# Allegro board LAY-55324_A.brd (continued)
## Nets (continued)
DCDC_3V3: C16.1 C35.1 C72.1 C73.1 C76.1 C78.1 C79.1 C85.1 C87.1 C97.1 C100.1 C102.1 C106.1 C112.1 C218.1 C225.1 C226.1 C233.1 C236.1 C238.1 C250.1 C252.1 C254.1 C261.1 C269.1 C274.1 C275.1 C278.1 C279.1 J2.36 J2.38 J3.36 J3.38 J62.1 J64.13 L1.1 L4.2 R15.1 R16.1 R22.1 R23.1 R32.1 R40.1 R41.1 R62.2 R69.1 R70.1 R71.1 R215.1 R216.1 R218.1 R286.1 R297.1 R298.1 R302.1 R307.1 R311.1 R312.2 R314.1 R374.2 R376.1 R378.1 R380.1 R382.1 SW64.1 TP215.1(PIN1) U3.7 U4.E9 U4.F10 U4.J10 U4.K4 U4.L1 U4.L2 U4.M9 U4.N14 U4.P12 U203.1 U203.3 U205.1 U207.5(VCCB) U208.5(VCCB) U212.5(VCCB) U213.1 U214.5 U217.1 U221.14(REFB) Y1.1 Y1.4(VDD)
DCDC_FB: R312.1 R315.1 U3.8
DCDC_SW: L4.1 U3.3
DM: CON60.A7 CON60.B7 L60.4 U1.2
DP: CON60.A6 CON60.B6 L60.1 U1.1
G: D60.3 R82.2
GPIO_AD_B0_01: J2.28 U4.H10
GPIO_AD_B0_01_EXT: J3.28 J64.11
GPIO_AD_B0_02: J2.51 U4.M11
GPIO_AD_B0_02_EXT: J3.51 J64.8
GPIO_AD_B0_03: J2.26 U4.G11
GPIO_AD_B0_03_EXT: J3.26 J64.6
GPIO_AD_B0_04: J61.3 R21.2 R22.2 U4.F11
GPIO_AD_B0_05: J61.1 R23.2 R24.2 U4.G14
GPIO_AD_B1_04: J2.39 U4.L12
GPIO_AD_B1_04_EXT: J3.39 J64.1
GPIO_AD_B1_12: J2.31 U4.H12
GPIO_AD_B1_12_EXT: J3.31 J64.5
GPIO_AD_B1_13: J2.27 U4.H11
GPIO_AD_B1_13_EXT: J3.27 J64.9
GPIO_AD_B1_15: J2.32 U4.J14
GPIO_AD_B1_15_EXT: J3.32 J64.7
GPIO_B0_04: C123.1 R37.2 SW62.1 SW62.2 U4.C8
GPIO_B0_05: J63.2 U4.B8
GPIO_B0_06: R32.2 R35.2 U4.A8
GPIO_B0_07: R38.2 R40.2 U4.A9
GPIO_B0_08: R36.2 U4.B9
GPIO_B0_09: C37.1 R42.2 SW61.1 SW61.2 U4.C9
GPIO_B0_10: R39.2 R227.2 U4.D9
GPIO_B0_11: J2.8 R34.2 U4.A10
GPIO_B0_11_EXT: J3.8 R235.2
GPIO_B0_12: R41.2 R78.2 U4.C10
GPIO_B0_13: R31.2 U4.D10
GPIO_B0_14: J2.14 R18.2 U4.E10
GPIO_B0_14_EXT: J3.14 U213.2
GPIO_B0_15: R77.2 U4.E11 U214.3
GPIO_B1_00: R224.2 U4.A11
GPIO_B1_02: J2.7 U4.C11
GPIO_B1_02_EXT: J3.7 J64.3
GPIO_B1_03: J2.9 U4.D11
GPIO_B1_03_EXT: J3.9 J64.4
I2C1_SCL: J2.33 R16.2 TP20.1(PIN1) U4.J11
I2C1_SCL_EXT: J3.33 J64.10
I2C1_SDA: J2.37 R15.2 TP17.1(PIN1) U4.K11
I2C1_SDA_EXT: J3.37 J64.12
JTAG_NTRST: J2.23 U4.G10
JTAG_NTRST_EXT: J3.23 J62.9
JTAG_TDI: J2.19 U4.F14
JTAG_TDI_EXT: J3.19 J62.8
JTAG_TDO: J2.30 U4.G13
JTAG_TDO_EXT: J3.30 J62.6
MIC_CLK_EXT: J2.70 R223.1
MIC_CLK_EXT_E: J3.70 R222.1 R365.2
MIC_DATA0_EXT: J2.66 R225.1
MIC_DATA0_EXT_E: J3.66 R243.2 R368.2
MIC_DATA1_EXT: J2.64 R229.1
MIC_DATA1_EXT_E: J3.64 R228.2 R367.2
MIKROBUS_PWM: J2.13 U4.C13
MIKROBUS_PWM_EXT: J3.13 J64.2
MODE0: J63.3 R65.2
MODE1: J63.1 R70.2
MQS_LEFT: J2.1 U4.E7
MQS_LEFT_EXT: J3.1 R43.2
MQS_RIGHT: J2.5 U4.D7
MQS_RIGHT_EXT: J3.5 R44.2
NVCC_SEMC_1V8_3V3: C82.1 C98.1 C99.1 R214.1 R215.2 U4.E6 U4.F5
OUT+: FB3.1 U6.C3
OUT-: FB4.1 U6.A3
OUTN: C32.1 FB4.2 TP61.1(TP)
OUTP: C31.1 FB3.2 TP63.1(TP)
POR_B: C4.1 C74.1 J2.4 R1.1 R69.2 TP214.1(PIN1) U4.M7
POR_B_E: J3.4 J62.10(B5) TP1.1(PIN1)
PSRAM_CLK: R277.2 R279.1 U4.D2
PSRAM_DATA0: R264.1 R265.1 U4.B3
PSRAM_DATA1: R266.1 R273.1 U4.A2
PSRAM_DATA2: R267.1 R274.1 U4.D1
PSRAM_DATA3: R268.1 R275.1 U4.E1
PSRAM_DATA4: R269.1 U4.A6
PSRAM_DATA5: R270.1 U4.B6
PSRAM_DATA6: R271.1 U4.B1
PSRAM_DATA7: R272.1 U4.A5
PSRAM_DQS: R281.1 U4.G2
PSRAM_RST_N: C277.1 R288.2 TP206.1(PIN1) U215.A4
PSRAM_SS0: R276.2 R278.1 U4.D3
QSPI_CLK: TP66.1(PIN1) U4.L4 U5.6
QSPI_DQ0: U4.P3 U5.5
QSPI_DQ1: U4.N4 U5.2
QSPI_DQ3_HOLDN: R30.2 U4.P5 U5.7
QSPI_SN: R17.2 U4.L3 U5.1
QSPI_WN_DQ2: R14.2 U4.P4 U5.3(W\P\/IO2)
R: D60.2(RED) R80.2
RF_50E: D1.2(A2) J1.1 R2.1
RGB_LED_B: R81.1 TP18.1(PIN1) U4.K10
RGB_LED_G: R82.1 TP19.1(PIN1) U4.J12
RGB_LED_R: R80.1 TP16.1(PIN1) U4.K12
RTC_XTALI: J2.48 R12.1
RTC_XTALI_EXT: J3.48 R293.1
RTC_XTALI_M2: R10.2 R293.2 R316.1 R322.2
SAI1_RX_BCLK_A: R49.1 R221.2 R362.2
SAI1_RX_BCLK_A_EXT: R222.2 R245.2 R254.2
SD1_CLK: J2.60 U4.J3
SD1_CLK_EXT: J3.60 R20.1
SD1_CMD: J2.52 U4.J4
SD1_CMD_EXT: J3.52 R29.2 R76.2
SD1_DATA0: J2.63 U4.J1
SD1_DATA0_EXT: J3.63 R25.2 R73.2
SD1_DATA1: J2.59 U4.K1
SD1_DATA1_EXT: J3.59 R19.2 R72.2
SD1_DATA2: J2.65 U4.H2
SD1_DATA2_EXT: J3.65 R27.2 R75.2
SD1_DATA3: J2.56 U4.J2
SD1_DATA3_EXT: J3.56 R26.2 R74.2
SHIELD: CON60.SH1 CON60.SH2 CON60.SH3 CON60.SH4 FB1.2
SWD_CLK/JCLK: J2.24 U4.F12
SWD_CLK/JCLK_EXT: J3.24 J62.4 TP60.1(PIN1)
SWD_DIO/TMS: J2.17 U4.E14
SWD_DIO/TMS_EXT: J3.17 J62.2 TP22.1(PIN1)
USB_DM: J2.45 U4.M8
USB_DM_EXT: J3.45 L60.3
USB_DP: J2.47 U4.L8
USB_DP_EXT: J3.47 L60.2
USB_OTG1_VBUS: C11.1 C77.1 FB2.2 U4.N6
WIFI_32K: R10.1 Y1.3
WL_3V3: C6.1 C7.1 C20.1 C21.1 C228.1 C229.1 C230.1 C231.1 J8.2 J8.4 J8.72 J8.74 L1.2 R357.1 TP5.1(PIN1) U2.9
WL_HOST_RST_N: J8.23 TP203.1(PIN1)
WL_HOST_WAKE: J2.55 TP12.1(PIN1) U4.L6
WL_HOST_WAKE_EXT: J3.55 R306.1
WL_HOST_WAKE_LS: R296.2 R304.2 R336.1 U221.3
WL_REG_ON: J2.41 U4.K7
WL_REG_ON_EXT: J3.41 R309.1 R318.1 TP4.1(PIN1)
WL_REG_ON_LS: R308.2 R341.1 U221.4
WL_SD1_CLK: C66.1 R20.2 R329.1 R330.2
WL_SD1_CMD: C63.1 R29.1 R328.1 R331.2
WL_SD1_DATA0: C67.1 R25.1 R324.1 R332.2
WL_SD1_DATA1: C68.1 R19.1 R325.1 R333.2
WL_SD1_DATA2: C61.1 R27.1 R326.1 R334.2
WL_SD1_DATA3: C62.1 R26.1 R327.1 R335.2
N99781670: L3.1 U4.M1 U4.M2
N99781683: R11.1 R12.2 U4.N9 Y3.1
N99781708: C23.1 R13.2 U4.N11 Y2.1
N101568785: C19.1 R8.1 R13.1 U4.P11 Y2.3
N101575953: C22.1 U4.P9 Y3.2
N101577088: C86.1 R71.2 U4.K3
N101638363: TP14.1(PIN1) U4.N12
N102042510: R1.2 SW60.1 SW60.2
N102115004: TP11.1(PIN1) U4.M6
N102548232: J61.2 R62.1
N102553145: R53.2 R226.1
N102553184: M1.1 R53.1
N102553251: M2.4 R221.1 R249.1
N102553371: R54.2 R244.2
N102577756: R72.1 R73.1 R74.1 R75.1 R76.1 R302.2 R303.1
N102592066: C28.1 C30.1 R44.1 R46.1
N102592074: C30.2 R48.2
N102592078: R48.1 U6.A1
N102592271: C27.1 C29.1 R43.1 R45.1
N102592279: C29.2 R47.2
N102645166: R33.1 U4.F13
N102680332: R47.1 U6.C1
N102764568: M2.1 R54.1
N102806355: C69.1 C71.1 U4.P8
N102806363: C75.1 C80.1 U4.P10
N102806393: C81.1 U4.M10
N102824760: C83.1 C89.1 R216.2 R217.1 U4.J6
N102954723: C221.1 C222.1 C223.1 R213.1 TP201.1(PIN1) U203.5(VOUT)
N102971023: R219.2 U205.4
N102971148: R49.2 R219.1 R223.2
N102972460: R260.1 R261.1 U205.2
N102974327: R224.1 U207.4
N102974329: R225.2 R226.2 R259.1 U207.2
N102974984: R227.1 U208.4
N102974986: R229.2 R244.1 R366.1 U208.2
N102975340: R230.2 R368.1
N102975342: M3.1 R230.1
N102975646: M4.1 R231.1
N102977151: R232.1 U209.6
N102977178: R232.2 R236.1 U212.2
N102981054: R237.2 R238.1 U209.2
N102981520: R235.1 U212.4
N102982227: R239.2 R240.1 U210.2
N102982627: R241.2 R242.1 U211.2
N102983525: R234.2 R243.1
N102983638: R233.2 R367.1
N102984339: M3.4 R245.1 R247.1
N102985542: M1.4 R362.1
N102986885: M4.4 R254.1
N102988264: R364.1 U209.4
N102988273: R252.1 R255.1 R363.2 R364.2 R365.1
N102988559: R256.2 U213.4
N102988816: R256.1 R257.1 U210.1(WS) U211.1(WS)
N102989280: R257.2 U209.1(WS)
N102995385: R260.2 U214.4(Y)
N102999315: D2.A R262.1 SW64.2
N102999320: R262.2 U214.6
N102999809: D2.C(CATHODE) R263.1
N103006469: R265.2 U215.D3
N103006492: R266.2 U215.D2
N103006515: R267.2 U215.C4
N103006538: R268.2 U215.D4
N103006561: R269.2 U215.D5
N103006584: R270.2 U215.E3
N103006607: R271.2 U215.E2
N103006630: R272.2 U215.E1
N103006767: R278.2 R282.2 U215.A3
N103006790: R279.2 R285.1 U215.B2
N103007378: R280.2 TP202.1(PIN1) U215.C2
N103007771: R281.2 U215.C3
N103012825: C227.1 J8.64 R218.2
N103019057: J8.20 R300.1
N103019687: J8.21 R304.1
N103019945: J8.56 R318.2
N103019994: J8.54(W\_\D\I\S\A\B\L\E\2\) R319.2
N103022078: R294.2 U221.8
N103022219: R295.1 R296.1 R378.2 R379.1
N103022552: R297.2 R301.2 U221.13
N103022554: R298.2 R306.2 U221.12
N103023474: R307.2 R309.2 U221.11
N103024377: R308.1 R310.1 R380.2 R381.1
N103024546: R311.2 R339.2 U221.10
N103030751: R313.2 R317.1 U3.5
N103030787: C276.1 U3.6
N103030825: R314.2 TP209.1(PIN1) U3.1
N103030906: R313.3 TP208.1(PIN1)
N103038120: J8.50 R316.2 R361.1
N103040281: C70.1 L61.1 U2.23
N103040289: L61.2 U2.21
N103040293: C60.1 R321.1 R357.2 U2.22
N103040458: R336.2 U2.13
N103040524: R325.2 U2.19
N103040539: R326.2 U2.14
N103040548: R327.2 U2.15
N103040555: R328.2 U2.16
N103040569: R329.2 U2.17
N103040633: C1.2 C2.1 R2.2
N103040687: R322.1 R323.1 U2.24
N103057784: R324.2 U2.18
N103058128: J8.17 R334.1
N103058131: J8.9 R330.1
N103058134: J8.11 R331.1
N103058137: J8.13 R332.1
N103058140: J8.19 R335.1
N103058143: J8.15 R333.1
N103059335: R337.1 R338.2 U2.34
N103060267: R340.1 R341.2 U2.12(W\L\_\D\I\S\)
N103061025: R345.1 U2.41
N103061028: R342.1 U2.44
N103061031: R343.1 U2.43
N103061034: R344.1 U2.42
N103061599: J8.32 R347.1
N103061602: J8.34 R348.1
N103061605: J8.22 R346.1
N103061608: J8.36 R349.1
N103061936: R352.1 U2.7
N103074237: R363.1 U211.4
N103074547: R255.2 U210.4
N103079715: R228.1 R231.2
N103090099: R273.2 U216.2
N103090100: R264.2 U216.5
N103090101: R275.2 U216.7
N103090102: R274.2 U216.3
N103091093: R276.1 R283.2 U216.1
N103091234: R277.1 R284.1 U216.6
N103097432: C262.1 R376.2 R377.1 U217.16(VCCB)
N103098361: R289.2 U217.14
N103098539: R290.2 U217.13
N103098580: R369.2 U217.12
N103098723: R370.2 U217.11
N103098760: R371.1 U217.3
N103098763: R372.1 U217.4
N103098875: R291.1 U217.5
N103098937: R292.1 U217.6
N103099207: R373.1 U217.9
N103099681: R374.1 U217.2 U217.15
N103100171: R375.1 U217.7 U217.10
N103106816: R384.2 TP216.1(PIN1)
N103106856: R386.2 TP218.1(PIN1)
N103106861: R385.2 TP217.1(PIN1)
N103107290: R384.1 U4.D12
N103107293: R385.1 U4.C12
N103107296: R386.1 U4.B12
N103163487: C36.1 J64.14 R387.1
N1029765922: R234.1 U210.6
N1029783922: R233.1 U211.6

Pads without a net: BMP60 1; BMP61 1; BMP62 1; BMP63 1; BMP64 1; CON60 A2 A3 A8 A10 A11 B2 B3 B8 B10 B11; J8 3 5 6 8 10 12 14 16 35 37 38 40 41 43 44 46 47 48 49 52 53 55 58 59 60 61 62 65 66 67 68 70 71 73; J62 7; NOREF#171 1; U1 3 5; U2 4 5 8 10 11 25 26 27 28 29 30 32 35 37 38 39 40; U4 A3 A4 A7 A12 A13 B2 B4 B7 B11 B13 C1 C2 C3 C4 C5 C6 C7 D4 D5 D6 D8 D13 D14 E3 E4 E5 E12 F1 F2 F3 F4 G1 G3 G4 G5 G12 H1 H3 H4 H5 H13 J13 L5 L7 L11 L13 M3 M4 M5 M12 M13 M14 N3 N7 N10 N13 P2 P6 P7 P13; U203 4; U215 A2 A5 B1 B5 C5; U221 6 9

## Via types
v1: diameter 0.457, hole 0.203, TOP to BOTTOM, 1178 vias
v2: diameter 0.457, hole 0.206, TOP to BOTTOM, 17 vias
v3: diameter 0.406, hole 0.203, TOP to BOTTOM, 76 vias
v4: diameter 0.457, hole 0.229, TOP to BOTTOM, 9 vias

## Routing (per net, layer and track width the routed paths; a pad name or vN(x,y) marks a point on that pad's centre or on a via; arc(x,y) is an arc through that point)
GND: length 493
  TOP w0.127: U4.A14 v3(142,33.53) ; U4.G7 v3(145.58,28.18) ; U4.K13 v3(147.53,32.08) ; U4.N5 v3(150.13,27.53) ; U4.A1 v3(141.68,24.28)
  TOP w0.229: U4.N1 v3(150.13,24.28) ; U4.N2 v3(150.13,24.93)
  TOP w0.254: U4.N8 v3(150.13,29.48) ; U4.E2 v3(144.93,24.93) ; U4.J7 v3(146.88,28.18) U4.H7 ; D60.1 v1(164,19.94) ; U4.P14 v3(150.62,33.54) ; U4.B5 142.65,27.2 v3(142.98,26.88) ; U4.K2 v3(148.18,24.93) ; U4.L9 v3(148.18,30.13) U4.K9 ; C22.2 v1(155.5,29.21) R11.2 ; U4.E13 v3(144.28,32.73) ; U4.J8 v3(146.88,29.48) ; U4.K6 v3(148.18,28.18) ; U1.4 99.7,46.36 v1(99.44,46.1) ; U4.G8 v3(145.58,29.48) ; U4.P1 v3(150.78,24.28) ; U4.H8 v3(146.88,28.83) ; U4.B10 v3(142.98,30.13)
  TOP w0.305: D1.1 4.07,22.14 ; D1.1 4.07,20.92 ; D1.1 3.38,21.46 ; D1.1 4.07,20.79 ; D1.1 3.51,21.46 ; D1.1 4.07,22.01 ; 4.27,17.17 J1.3 ; J1.3 5.8,17.17 ; J1.3 4.15,17.17 ; J1.3 5.93,17.17 ; J1.3 5.04,16.41 ; J1.3 5.04,16.28 ; J3.43 78.86,49.34 ; 130.9,50.37 SW60.3 ; SW60.3 130.9,53.62 ; SW60.3 129.68,51.99 ; U215.C1 v1(142.59,20.36) ; 137.82,27.66 R35.1 ; 3.57,17.17 J1.4 ; J1.4 3.57,20.17 ; J1.4 3.57,20.04 ; J1.4 3.57,17.3 ; J1.4 2.65,18.67 ; J1.4 2.78,18.67 ; J3.68 86.48,54.04 ; 4.02,26.47 C3.2 ; C3.2 4.02,27.64 ; C3.2 3.31,27.05 ; C3.2 3.44,27.05 ; v1(97.46,48.31) CON60.A12 97.14,48.29 ; 103.78,48.29 CON60.A1 v1(103.46,48.26) ; 129.68,43.1 SW60.4 130.9,44.73 ; D60.1 164.77,19.04 ; 129.68,11.18 SW62.4 ; 49.47,33.93 U212.3 ; U212.3 50.27,34.53 ; U212.3 48.67,34.53 ; 137.61,27.08 R37.1 ; 12.95,17.32 C278.2 ; 9.64,44.24 Y1.2 10.63,43.15 ; 13.34,36.15 U2.20 ; J8.51 v1(38.43,40.78) ; 28.41,52.42 J64.15 26.35,52.42 ; v2(142.42,5.97) 142.42,6.74 ; v2(142.42,5.97) 143.19,5.97 ; v2(142.42,5.97) 141.64,5.97 ; v1(44.43,40.78) J8.75 44.54,40.85 ; J3.20 71.24,54.04 ; J1.2 7.29,18.67 ; J1.2 6.51,17.17 ; J1.2 6.51,20.17 ; J1.2 6.51,20.04 ; J1.2 6.51,17.3 ; R249.2 130.91,5.89 ; R249.2 130.91,4.22 ; R249.2 131.75,5.05 ; C7.2 13.14,25.46 ; J8.69 v1(42.93,40.78) ; C279.2 12.7,20.4 ; 94.74,8.24 C122.2 ; C70.2 14.59,41.45 ; U215.B3 144.59,19.35 v1(144.59,19.36) ; C6.2 12.94,24.32 ; U203.2 158.71,11.21 ; v1(33.93,40.78) J8.33 33.7,40.85 ; J3.62 84.57,54.04 ; 129.87,18.44 SW62.3 ; 130.9,38.25 SW61.3 ; 130.9,29.36 SW61.4 ; U2.36 3.93,36.61 ; R259.2 163.25,15.57 ; C21.2 13.14,26.36 ; J8.7 27.43,40.89 v1(27.3,40.77) ; R240.2 2.29,53.54 ; R240.2 3,52.83 ; R240.2 1.57,52.83 ; 18.03,46.72 J62.3 ; J8.63 v1(41.43,40.78) ; 26.47,46.09 J64.16 ; 65.17,54.04 J3.2 ; 3.44,24.26 C2.2 ; C2.2 4.02,23.55 ; C2.2 4.02,23.67 ; C2.2 4.02,24.84 ; C2.2 3.31,24.26 ; 99.16,46.74 U1.4 ; J3.54 82.03,54.04 ; J8.57 v1(39.93,40.78) ; J3.12 68.7,54.04 ; 10.61,41.46 R323.2 ; Y2.4 155.58,34.76 ; 5.94,38.61 U2.31 ; 3.49,39.5 U2.33 4.14,38.61 ; J8.39 v1(35.43,40.78) ; J8.45 v1(36.93,40.78) ; J3.49 80.64,49.34 ; 96.57,51.41 CON60.B1 ; C20.2 12.99,26.26 ; J3.16 69.97,54.04 ; J8.1 v1(25.93,40.77) ; v1(30.18,35.81) J8.18 ; CON60.B12 104.35,51.41 ; J3.6 66.79,54.04 ; 151.84,50.01 v2(152.58,49.28) ; 150.51,4.41 SW64.3 ; 8.69,44.83 C16.2 ; U215.E5 v1(140.59,16.36) ; 19.3,46.72 J62.5 ; v2(153.97,36.83) 154.75,36.83 ; J3.58 83.3,54.04
  TOP w0.356: J3.11 68.58,49.02 v1(68.2,49.4) ; J3.15 69.85,49.02 v1(69.47,49.4) ; v1(80.64,45.97) J3.49 ; J3.61 84.45,46.23 v1(84.71,45.97) ; v1(75.56,50.67) J3.34 ; v1(66.67,54.1) J3.6 ; v1(73.28,45.97) 73.02,46.23 J3.25 ; v1(84.45,54.1) J3.62 ; J3.46 79.38,50.93 v1(79.63,50.67) ; v1(69.85,54.1) J3.16 ; J3.43 78.74,49.02 v1(78.36,49.4) ; J3.57 83.18,46.23 v1(83.44,45.97) ; v1(81.91,54.1) J3.54 ; v1(66.04,45.97) J3.3 ; v1(83.18,54.1) J3.58 ; v1(72.01,45.97) 71.75,46.23 J3.21 ; v1(71.12,54.1) J3.20 ; v1(64.64,52.39) J3.2 ; v1(86.36,54.1) J3.68 ; v1(68.58,54.1) J3.12
  TOP w0.381: SW60.4 130.85,43.05 v1(129.72,43.05) ; Y2.2 154.41,32.08 155.27,31.21 v1(155.27,31.21) C19.2 156.44,31.07 R8.2 ; U2.20 v1(13.24,36.61) ; v1(161.09,10.03) 161.09,10.59 U207.3 ; R31.1 v1(137.85,35.81) ; v1(51.56,20.07) 51.56,19.38 U213.3 ; C122.2 94.11,9.52 93.73,9.91 v1(93.73,10.92) ; C122.2 95.39,9.52 95.77,9.91 v1(95.77,10.92) ; C122.2 v1(94.74,10.92) ; CON60.B12 v1(103.51,51.56) ; v1(97.41,49.91) CON60.B1 v1(97.41,51.56) ; R35.1 R37.1 v1(137.85,27.56) ; C218.2 v1(160.45,9.65) ; U212.3 49.4,34.47 v1(49.4,33.78) ; J64.16 v1(26.16,47.08) ; Y2.4 153.98,35.06 v1(153.06,35.98) C23.2 ; R38.1 R42.1 v1(137.85,30.48) ; R34.1 v1(137.85,31.62) ; R39.1 v1(137.85,33.78) ; R36.1 v1(137.85,32.77) ; v1(156.77,11.56) 156.26,11.43 C221.2 ; U203.2 v1(158.42,11.56) ; U2.36 v1(2.07,36.61) ; R18.1 v1(137.85,36.83) ; R323.2 v1(10.41,40.77) ; R259.2 v1(163.88,14.73)
  TOP w0.508: SW62.3 v1(130.9,18.54) ; C20.2 v1(13.21,25.91) ; C21.2 v1(13.33,27.05) ; U2.33 v1(4.14,40.44) ; J64.15 v1(27.38,54.48) ; SW61.3 v1(129.72,39.88) ; U2.31 v1(5.94,40.44) ; SW64.3 v1(150.51,6.6) ; J62.5 v1(19.3,50.29) ; Y1.2 10.33,43.94 v1(9.4,43.94) C16.2 ; C279.2 v1(13.84,19.68) ; R240.2 2.24,52.88 2.24,53.93 ; SW61.4 v1(130.9,32.51) ; SW62.4 v1(130.9,12.7) ; C7.2 v1(13.33,24.77) ; C6.2 v1(13.21,23.62) ; C11.2 v1(153.21,28.45) ; C70.2 v1(14.99,40.75) ; C278.2 v1(14.22,18.29) ; J62.3 v1(18.03,50.32)
  L2_GND w0.305: 151.88,39.12 TP210.1 ; TP210.1 152.7,39.94 ; TP210.1 153.53,39.12 ; TP210.1 152.7,38.29 ; 156.07,39.12 TP213.1 ; TP213.1 156.9,39.94 ; TP213.1 156.9,38.29 ; TP213.1 157.72,39.12 ; TP221.1 139.31,39.62 ; TP221.1 138.48,38.8 ; TP221.1 137.65,39.62 ; TP221.1 138.48,40.45
  BOTTOM w0.102: v3(145.58,29.48) 145.54,29.48 145.15,29.86 145.15,29.9 144.93,30.12 C101.2
  BOTTOM w0.203: C97.2 144.2,28.75 143.79,28.35 143.79,28.21 C90.2
  BOTTOM w0.254: C76.2 150.13,29.48 v3(150.13,29.48) ; C112.2 148.18,27.55 v3(148.18,28.18) ; v3(144.28,27.53) 143.97,27.53 143.76,27.74 143.76,28 C90.2 ; U6.A2 97.28,3.3 v1(97.41,3.17) ; C108.2 146.23,26.76 v3(146.23,26.23) 146.23,25.62 C107.2 ; C106.2 146.88,32.08 v3(147.53,32.08) ; v3(145.58,29.48) 145.6,29.46 C94.2 ; v3(144.93,24.93) 144.76,25.09 C98.2 ; v3(150.13,27.53) 150.19,27.47 C77.2 ; U217.8 60.19,29.46 60.45,29.21 60.71,29.21 v1(60.96,28.96) R373.2 ; v3(148.18,30.13) 147.57,30.13 C84.2 ; C83.2 145.58,25 v3(145.58,25.58) C92.2 ; R375.2 v1(63.5,28.83) ; v3(145.58,28.18) 145.59,28.17 C96.2 ; R33.2 144.26,32.75 v3(144.28,32.73) C85.2 ; U6.B3 v1(98.55,4.57) ; C82.2 141.68,25.04 v3(141.68,24.28) ; C86.2 v3(148.18,24.93) ; C99.2 v3(142.98,26.88)
  BOTTOM w0.279: C26.2 v1(151.69,12.95) ; U5.4 v1(156.51,25.27) ; C25.2 v1(152.7,12.95)
  BOTTOM w0.305: 143.13,3.94 R263.2 142.29,4.78 ; C269.2 67.71,20.3 ; 131.42,14.1 C239.2 132.26,14.94 ; 60.78,26.46 U221.7 62.06,27.21 ; C256.2 149.47,11.59 ; C74.2 158.17,38.94 ; C74.2 157.45,38.19 ; C74.2 158.88,38.19 ; 62.72,28.81 R375.2 ; 2.92,36.12 R337.2 3.76,36.96 ; C233.2 133.86,40.13 ; 159.05,14.81 C222.2 160.02,13.72 ; 60.45,27.61 R373.2 61.29,28.45 ; 133,14.71 U208.3 ; 6.3,2.79 4.62,2.79 ; J2.54 155.89,53.56 ; 18.03,39.7 C68.2 17.2,38.86 ; 48.44,19.18 C253.2 ; v3(150.62,33.54) 150.47,33.4 C78.2 150.47,32.27 C81.2 ; v2(152.58,49.28) J2.43 152.58,46.52 ; C38.2 164.21,7.31 ; 60.81,11.71 R317.2 ; C245.2 48.46,31.82 ; C87.2 149.87,24.38 ; v1(61.72,9.02) R315.2 62.48,8.18 ; C41.2 164.16,7.21 ; C73.2 151.27,33.75 ; C271.2 63.7,15.57 ; 138.54,52.14 J2.2 ; C261.2 60.45,36.14 ; 134.05,16.51 C123.2 ; C79.2 151.15,34.19 ; 134.09,40.39 C37.2 135.76,40.39 ; C272.2 64.01,15.57 ; 26.87,47.92 C36.2 26.87,46.24 ; R361.2 39.07,37.85 ; C226.2 160.02,9.4 ; C249.2 3.43,7.7 ; 137.45,39.62 TP221.1 ; TP221.1 138.48,40.65 ; TP221.1 139.51,39.62 ; R79.2 99.08,8.02 ; 149.09,22.56 C91.2 ; C273.2 65.63,15.09 ; 97.66,49.99 C10.2 97.66,48.31 ; 152.7,38.09 TP210.1 ; TP210.1 153.73,39.12 ; TP210.1 151.68,39.12 ; C5.2 103.25,51.51 ; 148.06,21.04 C24.2 ; v1(43.56,35.83) C229.2 42.72,35.07 ; 17.91,48.69 C35.2 18.75,49.53 ; 26.01,30.71 C231.2 ; 63.12,21.08 63.9,21.87 ; C89.2 147.49,28.83 v3(146.88,28.83) 146.31,28.83 C95.2 ; C262.2 60.22,36.09 ; 134.67,41.96 C4.2 ; C71.2 153.17,29.06 ; 51.36,26.14 R238.2 ; 146.86,46.52 J2.25 ; 136.35,15.09 C238.2 ; 156.51,23.37 U5.4 157.29,24.35 ; 164.08,10.79 C236.2 163.25,9.96 ; 98.04,51.49 R3.2 97.21,52.32 ; J2.58 157.16,53.56 ; C242.2 7.61,7.74 ; 9.13,49.34 C240.2 ; C258.2 v1(142.59,20.36) ; C80.2 152.79,31.9 ; 156.9,38.09 TP213.1 ; TP213.1 155.87,39.12 ; TP213.1 157.93,39.12 ; 150.86,13.13 C26.2 ; J2.20 145.1,53.56 ; U214.2 134.22,37.69 ; 50.55,33.83 R236.2 ; C257.2 v1(144.59,19.36) ; 149.8,24.87 C102.2 ; 47.78,31.82 C244.2 ; 17.25,30.5 C62.2 ; 152.78,32.85 C72.2 152.07,33.61 ; 50.78,33.89 C250.2 ; 11.06,55.03 R247.2 11.9,54.19 ; C254.2 130.07,38.97 ; v2(154.61,20.45) 157.73,20.45 ; 131.35,43.28 U205.3 130.63,42.35 ; 43.67,35.85 C228.2 v1(45.21,35.07) ; C241.2 9.68,49.34 ; J2.6 140.65,53.56 ; 17.2,32 C63.2 ; 17.2,34.29 C66.2 ; C225.2 159.26,10.67 ; C230.2 26.56,30.71 ; 151.1,10.16 R24.1 ; C243.2 9.41,7.68 ; C223.2 159.26,12.45 ; 17.14,27.61 R340.2 ; C232.2 133.64,47.34 ; C69.2 153.17,28.6 ; J2.62 158.43,53.56 ; 134.22,37.91 U214.1 133.2,38.78 ; C246.2 4.8,49.46 ; J2.12 142.56,53.56 ; 4.12,49.46 C247.2 ; 138.15,36.83 138.99,36.83 ; C255.2 v1(140.59,16.36) ; 141.66,24.38 C82.2 ; 13.97,36.12 C60.2 13.13,36.96 ; J2.16 143.83,53.56 ; 103.25,48.18 R5.2 ; 17.2,27.43 C61.2 ; 136.4,22.48 R65.1 135.56,21.64 ; J2.68 160.34,53.56 ; C252.2 52.4,19.18 ; 17.2,36.58 C67.2 ; C100.2 152.02,36.66 ; C75.2 v1(153.08,30.85) ; 130.28,41.15 R261.2 ; 160.25,10.79 C237.2 ; 48.56,34.67 C251.2
  BOTTOM w0.356: J2.16 v1(143.69,53.47) ; J2.57 v1(157.02,49.27) ; J2.25 146.86,49.02 v1(146.61,49.28) ; J2.58 v1(157.02,53.47) ; J2.15 v1(143.69,49.27) ; J2.54 v1(155.75,53.47) ; J2.62 v1(158.29,53.47) ; J2.12 v1(142.42,53.47) ; J2.6 v1(140.51,53.47) ; J2.20 v1(144.96,53.47) ; J2.68 v1(160.2,53.47) ; J2.34 v1(149.4,53.47) ; J2.46 v1(153.21,53.47) ; J2.2 v1(139.24,53.47) ; J2.11 v1(142.42,49.27) ; v1(145.34,49.28) 145.59,49.02 J2.21 ; J2.49 v1(154.48,49.27) ; J2.3 v1(139.88,49.27) ; J2.61 v1(158.29,49.28)
  BOTTOM w0.381: C251.2 v1(49.4,33.78) ; 94.11,5.08 v1(93.34,5.08) ; C241.2 v1(8.9,49.36) ; R340.2 17.78,28.45 v1(18.03,28.7) C62.2 ; R46.2 v1(92.2,4.32) C28.2 ; C36.2 v1(26.16,47.08) ; C252.2 v1(51.56,20.07) ; C231.2 v1(26.8,30.73) ; C114.2 v1(93.34,4.06) ; U221.7 v1(63.25,26.46) ; C24.2 148.77,21.29 v1(148.41,21.64) ; C27.2 v1(92.2,4.95) R45.2 ; C60.2 v1(13.24,36.61) ; R252.2 v1(6.91,52.12) ; R238.2 50.75,26.97 v1(50.42,27.3) ; C261.2 v1(61.21,35.31) ; R261.2 v1(130.48,41.53) U205.3 ; R5.2 v1(103.46,48.26) ; C240.2 v1(9.92,49.36) ; C277.2 v1(145.52,15.16) ; C247.2 v1(4.9,49.48) ; C236.2 v1(162.36,10.79) ; C237.2 v1(161.09,10.03) ; C259.2 v1(138.35,9.65) ; C260.2 v1(138.34,10.71) ; C63.2 v1(18.03,30.99) ; R285.2 144.09,21.87 v1(143.6,22.36) ; C68.2 v1(18.03,37.85) ; v1(51.56,33.78) C250.2 R236.2 ; C61.2 v1(18.03,26.54) ; C100.2 v1(151.31,37.34) ; C67.2 v1(18.03,35.56) ; C239.2 v1(132.77,14.86) 133.46,14.16 U208.3 ; v1(2.07,36.61) 2.41,36.96 R337.2 ; 10.12,54.19 R247.2 ; 10.12,54.19 v1(9.91,53.98) ; 10.12,54.19 10.12,54.19 ; R79.2 v1(98.3,8) ; C253.2 v1(49.28,20.07) ; C230.2 v1(25.78,30.73) ; C246.2 v1(4.01,49.48) ; C227.2 v1(40.77,30.1) ; TP213.1 157.53,38.48 157.87,38.48 C74.2 ; C66.2 v1(18.03,33.4) ; C262.2 v1(59.44,36.07) ; R317.2 v1(60.83,10.92)
  BOTTOM w0.508: R366.2 v1(134.54,9.65) ; C123.2 v1(135.81,16.51) ; 63.12,21.08 v1(63.12,21.84) ; C256.2 v1(147.93,11.59) ; C4.2 v1(133.65,42.8) ; C40.2 v1(130.99,5.79) ; C41.2 163.37,6.04 v1(163.12,5.79) ; C88.2 v1(149.53,37.47) ; U214.2 v1(132.26,36.96) ; v1(18.03,50.32) 17.91,50.19 C35.2 ; v1(135.18,41.4) 134.92,41.15 C37.2 ; 5.46,2.79 v1(5.46,2.03) ; C39.2 v1(131.24,8.08) ; C93.2 v1(150.39,18.07) ; C238.2 v1(136.83,14.86) ; v1(3.94,6.35) 3.94,6.35 C248.2 ; R65.1 v1(134.67,22.48) ; R24.1 v1(151.94,10.92) ; R284.2 v1(140.98,13.25) ; U214.1 v1(132.26,37.91) ; C269.2 v1(66.93,21.84) ; R361.2 v1(38.23,38.73) ; R263.2 v1(141.27,3.94) ; v1(163.37,8.08) C38.2 ; C232.2 v1(133.4,46.86) ; C233.2 v1(133.02,39.37) ; C254.2 v1(129.59,38.86)
  vias: v1(1.27,30.38) v1(1.37,55.68) v1(1.35,40.69) v1(1.42,8.89) v1(1.45,50.47) v1(1.47,1.37) v1(2.01,28.46) v1(2.01,27.7) v1(2.01,26.94) v1(2.01,26.17) v1(2.01,25.41) v1(2.01,24.65) v1(2.01,23.89) v1(2.01,23.13) v1(2.01,22.36) v1(2.01,21.6) v1(2.01,20.84) v1(2.01,20.08) v1(2.01,19.32) v1(2.01,18.55) v1(2.01,17.79) v1(2.01,17.03) v1(2.01,16.27) v1(2.01,15.34) v1(2.11,33.96) v1(2.16,55.05) v1(2.16,53.91) v1(2.16,3.05) v1(2.16,1.9) v1(2.61,19.61) v1(2.61,18.85) v1(2.61,18.09) v1(2.68,17.33) v1(2.81,26.15) v1(2.77,25.11) v1(2.79,23.37) v1(2.77,22.38) v1(2.77,15.34) v1(3.09,20.21) v1(3.28,47.22) v1(3.3,28.32) v1(3.3,27.05) v1(3.3,24.26) v1(3.3,21.46) v1(3.34,25.61) v1(3.36,22.86) v1(3.42,17.13) v1(3.53,15.34) v1(3.84,24.98) v1(3.87,22.17) v1(3.94,7.37) v1(4.11,16.81) v1(4.11,9.22) v1(4.14,29.21) v1(4.24,26.31) v1(4.24,23.52) v1(4.29,15.34) v1(4.35,25.55) v1(4.35,22.77) v1(4.45,55.05) v1(4.45,53.91) v1(4.45,3.05) v1(4.45,1.9) v1(4.62,16.25) v1(4.67,33.15) v1(5,29.31) v1(5.05,15.34) v1(5.38,16.25) v1(5.69,48.92) v1(5.79,25.4) v1(5.8,23.12) v1(5.82,15.34) v1(5.84,26.16) v1(5.84,24.64) v1(5.84,23.88) v1(5.84,22.36) v1(5.84,21.59) v1(5.94,29.21) v1(5.94,27.38) v1(5.96,16.74) v1(6.12,36.6) v1(6.35,9.4) v1(6.51,22.86) v1(6.6,25.15) v1(6.6,24.38) v1(6.6,23.62) v1(6.6,22.11) v1(6.6,21.35) v1(6.62,17.13) v1(6.58,15.34) v1(6.65,49.56) v1(7.04,20.21) v1(7.14,26.46) v1(7.14,25.69) v1(7.14,22.65) v1(7.34,15.34) v1(7.62,55.12) v1(7.62,53.98) v1(7.62,3.05) v1(7.62,1.9) v1(7.75,7.62) v1(7.9,33.12) v1(7.9,27.29) v1(7.9,26.53) v1(7.9,25.77) v1(7.9,25) v1(7.9,24.24) v1(7.9,23.48) v1(7.9,22.72) v1(7.9,21.96) v1(7.9,21.19) v1(7.9,20.43) v1(7.9,19.67) v1(7.9,18.91) v1(7.9,18.15) v1(7.9,17.38) v1(7.9,16.62) v1(7.9,15.86) v1(8.59,47.27) v1(8.59,45.01) v1(8.63,7.66) v1(9.91,55.12) v1(9.91,3.05) v1(9.91,1.9) v1(9.98,32.28) v1(10.41,27.28) v1(10.41,25.83) v1(10.62,8.25) v1(10.69,23.32) v1(10.82,16.21) v1(10.97,7.72) v1(10.95,4.67) v1(11.1,55.22) v1(11.2,36.6) v1(11.2,31.52) v1(11.28,49.23) v1(11.71,30.51) v1(12.12,17.5) v1(12.19,54.15) v1(12.32,52.68) v1(12.6,43.13) v1(13.21,30.86) v1(13.21,29.46) v1(14,52.17) v1(14.27,42.7) v1(14.4,41.63) v1(14.4,8.76) v1(15.11,22.73) v1(15.7,15.27) v1(15.77,44.55) v1(15.98,47.55) v1(16.41,13.64) v1(16.79,43.38) v1(17.14,46.71) v1(18.01,46.66) v1(18.14,39.83) v1(18.14,22.76) v1(18.29,20.95) v1(18.36,55.65) v1(18.52,45.16) v1(18.62,12.93) v1(18.8,1.42) v1(19.28,46.66) v1(19.76,43.08) v1(20.09,39.95) v1(20.12,26.47) v1(21.36,11.2) v1(21.36,6.12) v1(21.46,20.95) v1(21.54,16.38) v1(22.02,1.37) v1(22.15,55.6) v1(22.23,43.03) v1(22.71,51.1) v1(22.73,48.06) v1(22.73,46.99) v1(23.8,26.85) v1(23.88,29.39) v1(24.03,48.64) v1(24.18,52.25) v1(24.41,28.5) v1(25.27,33.96) v1(25.81,45.95) v1(26.11,48.56) v1(26.14,38.66) v1(26.26,50.52) v1(26.26,37.29) v1(26.44,11.2) v1(26.44,6.12) v1(26.62,28.24) v1(27.03,35.66) v1(28.04,35.66) v1(28.04,26.75) v1(28.5,50.52) v1(28.75,52.22) v1(28.93,40.11) v1(29.01,29.87) v1(29.03,28.24) v1(30.68,39.24) v1(31.19,52.25) v1(31.24,20.83) v1(31.7,40.82) v1(32.03,25.27) v1(32.31,13.23) v1(32.41,39.04) v1(32.46,35.97) v1(33.88,52.22) v1(33.86,25.3) v1(34.16,39.85) v1(34.54,24.54) v1(35.48,25.1) v1(36.6,26.44) v1(36.6,21.36) v1(37.36,35.92) v1(37.46,16.51) v1(37.85,13.23) v1(38.43,25.07) v1(38.96,36.04) v1(39.6,26.01) v1(41.61,39.04) v1(41.68,26.44) v1(41.68,21.36) v1(41.68,11.2) v1(41.68,6.12) v1(42.65,22.61) v1(42.77,50.43) v1(42.8,29.46) v1(43.33,1.9) v1(44.42,39.75) v1(44.42,21.31) v1(45.29,33.15) v1(45.42,22.35) v1(45.34,21.11) v1(46.3,46.33) v1(46.33,48.29) v1(46.43,37.67) v1(46.56,53.62) v1(46.76,11.2) v1(46.76,6.12) v1(46.99,42.16) v1(46.99,40.51) v1(47.68,31.8) v1(47.96,50.65) v1(48.03,12.93) v1(48.13,27.3) v1(48.13,26.16) v1(48.26,16.51) v1(48.44,34.32) v1(48.56,31.8) v1(48.64,42.93) v1(49.33,22.4) v1(49.61,12.5) v1(50.04,41.66) v1(50.04,39.9) v1(50.14,31.83) v1(50.42,26.16) v1(50.44,16.08) v1(51.05,48.13) v1(51.49,14.5) v1(51.84,6.12) v1(52.5,46.3) v1(52.53,17.5) v1(52.58,10.57) v1(52.7,31.75) v1(53.16,35.18) v1(54.38,22.45) v1(55.22,18.01) v1(55.73,21.11) v1(55.75,40.06) v1(55.78,28.6) v1(55.83,27.1) v1(56.03,36.04) v1(56.85,21.11) v1(56.92,16.28) v1(56.92,6.12) v1(57.4,18.9) v1(57.53,53.62) v1(57.81,28.73) v1(60.38,26.42) v1(60.53,17.96) v1(61.65,1.47) v1(61.93,33.76) v1(62.05,28.5) v1(62.08,27.66) v1(62.43,18.16) v1(62.48,7.87) v1(62.61,15.49) v1(63.5,15.49) v1(63.63,20.29) v1(63.73,8.23) v1(64.26,28.63) v1(64.36,22) v1(64.39,15.49) v1(64.52,53.64) v1(64.74,7.67) v1(64.87,49.35) v1(64.87,18.49) v1(65.2,43.36) v1(65.15,14.86) v1(65.38,34.47) v1(65.99,30.38) v1(66.04,1.45) v1(66.14,50.62) v1(66.7,12.09) v1(66.73,11.43) v1(66.73,10.79) v1(66.73,10.16) v1(67.03,34.11) v1(67.08,31.52) v1(67.08,6.12) v1(67.64,20.09) v1(68.38,27.41) v1(69.34,6.35) v1(69.6,21.79) v1(69.85,25.02) v1(69.98,26.92) v1(69.98,23.37) v1(70.08,15.04) v1(70.82,7.37) v1(71.3,41.1) v1(71.32,30.18) v1(71.37,20.07) v1(71.5,35.05) v1(71.45,13.16) v1(71.6,9.75) v1(72.16,31.52) v1(72.16,11.2) v1(72.16,6.12) v1(73.13,27.41) v1(73.05,21.41) v1(73.3,23.42) v1(73.41,35.05) v1(73.48,30.2) v1(74.42,27.43) v1(74.55,31.5) v1(74.73,23.09) v1(74.96,29.29) v1(75.34,54.51) v1(77.24,41.68) v1(77.24,26.44) v1(77.24,21.36) v1(77.24,11.2) v1(77.24,6.12) v1(79.55,20.65) v1(80.92,1.4) v1(81.25,24.43) v1(82.32,31.52) v1(82.32,26.44) v1(82.32,21.36) v1(82.32,16.28) v1(82.45,36.25) v1(84.33,38.23) v1(84.3,36.3) v1(85.57,1.47) v1(85.83,29.39) v1(85.85,36.17) v1(87.4,31.52) v1(87.4,26.44) v1(87.4,21.36) v1(87.4,16.28) v1(87.4,11.2) v1(87.4,6.12) v1(87.93,51.33) v1(88.04,38.56) v1(88.14,42.16) v1(88.87,46.2) v1(88.95,44.15) v1(89.05,51.16) v1(89.89,3.66) v1(90.04,6.25) v1(92.48,51.84) v1(92.48,41.68) v1(92.48,36.6) v1(92.48,31.52) v1(92.48,26.44) v1(92.48,21.36) v1(92.48,16.28) v1(92.58,49.2) v1(94.89,46.33) v1(96.32,44.88) v1(96.95,55.73) v1(97.56,41.68) v1(97.56,26.44) v1(97.56,21.36) v1(98.76,55.73) v1(99.06,5.33) v1(99.06,3.81) v1(99.19,4.57) v1(99.24,48.26) v1(101.68,55.75) v1(101.73,52.58) v1(101.73,51.82) v1(102.64,51.84) v1(102.64,41.68) v1(102.64,36.6) v1(102.64,26.44) v1(102.64,21.36) v1(102.64,16.28) v1(102.64,11.2) v1(103.94,55.75) v1(104.6,48.39) v1(107.72,51.84) v1(107.72,41.68) v1(107.72,36.6) v1(107.72,21.36) v1(107.72,16.28) v1(107.72,11.2) v1(112.8,46.76) v1(112.8,41.68) v1(112.8,36.6) v1(112.8,21.36) v1(112.8,16.28) v1(112.8,11.2) v1(112.8,6.12) v1(117.88,51.84) v1(117.88,46.76) v1(117.88,41.68) v1(117.88,26.44) v1(117.88,21.36) v1(117.88,11.2) v1(117.88,6.12) v1(119.25,55.52) v1(119.51,1.45) v1(122.96,41.68) v1(122.96,31.52) v1(122.96,26.44) v1(122.96,21.36) v1(122.96,11.2) v1(124.61,6.48) v1(124.64,50.47) v1(128.98,44.78) v1(128.98,1.3) v1(129.08,55.6) v1(129.06,48.97) v1(129.51,11.18) v1(129.57,10.11) v1(129.72,51.94) v1(129.64,16.21) v1(129.64,12.8) v1(129.84,3.63) v1(129.84,2.23) v1(130.02,32.77) v1(130.05,29.26) v1(130.38,48.11) v1(131.52,16.76) v1(131.55,53.75) v1(131.55,50.29) v1(131.83,27.58) v1(131.9,32.77) v1(131.85,29.16) v1(131.88,3.63) v1(131.88,2.23) v1(133.07,55.68) v1(133.4,33.07) v1(133.48,52.83) v1(133.65,44.22) v1(134.01,18.54) v1(134.24,5.33) v1(134.39,50.47) v1(134.39,45.16) v1(134.62,46.48) v1(135.48,46.53) v1(135.64,17.86) v1(135.71,1.37) v1(136.25,45.24) v1(136.35,24.79) v1(136.78,46.84) v1(136.8,28.14) v1(136.91,48.46) v1(137.13,18.34) v1(138,41.83) v1(138.38,52.04) v1(138.43,14.73) v1(138.68,40.82) v1(138.89,44.55) v1(139.73,45.8) v1(139.78,1.37) v1(140.82,6.02) v1(141,11.56) v1(141.1,15.14) v1(141.53,44.63) v1(141.63,14.5) v1(141.86,5.33) v1(143.18,37.08) v1(143.21,11.38) v1(143.33,3.23) v1(143.51,5.97) v1(143.61,5) v1(143.69,13.11) v1(143.84,14.52) v1(143.99,9.22) v1(144.42,44.68) v1(145.16,5.46) v1(145.52,3.43) v1(146.56,8.25) v1(146.94,5.21) v1(147.96,5.21) v1(148.46,6.6) v1(148.82,8.99) v1(149.96,50.14) v1(150.88,55.7) v1(151.05,23.37) v1(151.03,4.17) v1(151.18,21.72) v1(151.36,42.7) v1(151.43,33.66) v1(151.56,5.64) v1(153.67,37.47) v1(153.67,11.1) v1(154.1,44.2) v1(154.43,6.73) v1(154.69,14.02) v1(154.84,1.42) v1(155.24,45.21) v1(155.52,30.12) v1(155.55,37.36) v1(155.78,34.82) v1(155.78,8.97) v1(155.85,26.01) v1(155.93,44.17) v1(155.96,42.24) v1(156.44,23.34) v1(157,33.22) v1(157.35,28.04) v1(157.35,11.58) v1(158.06,14.76) v1(158.93,11.94) v1(158.93,11.18) v1(158.98,44.22) v1(158.95,1.37) v1(159.36,20.22) v1(159.44,11.56) v1(159.44,6.86) v1(159.66,49.71) v1(160.12,15.95) v1(161.26,15.95) v1(161.7,51.03) v1(161.7,49.05) v1(161.98,19.84) v1(161.98,3.63) v1(161.98,2.23) v1(163.53,15.62) v1(164.01,3.63) v1(164.01,2.23) v1(164.67,55.52) v1(164.82,51.61) v1(164.74,48.39) v1(164.8,42.77) v1(164.77,33.58) v1(164.74,21.77) v1(164.8,1.32) v1(164.87,6.78) v1(164.85,5.46) v2(59.94,32.13) v2(59.94,31.37) v2(59.94,30.61)
VBUS_5V: length 47.6
  TOP w0.381: v1(80.64,50.67) J3.50 v1(80.64,54.1)
  TOP w0.508: R6.2 162.48,21.21 162.99,21.72 162.99,46 160.45,48.54 160.45,50.67 158.55,52.58 155.37,52.58 v1(154.48,53.47)
  BOTTOM w0.254: C273.1 65.16,13.08 U3.2 ; U6.B2 U6.B1
  BOTTOM w0.356: J2.50 v1(154.48,53.47)
  vias: v1(61.09,13.59) v1(61.59,12.95) v1(61.85,12.19) v1(62.64,12.17) v1(95.88,5.21) v1(95.88,4.57) v1(95.88,3.94)
VBUS_5VDD: length 87.8
  TOP w0.305: 112.01,52.31 J60.2 ; J60.2 112.01,54.37 ; J60.2 110.98,53.34 ; J60.2 113.04,53.34 ; 86.36,46.16 J3.67 86.36,49.21 ; 86.99,46.16 J3.69 ; J3.69 87.44,47.69 ; J3.69 86.99,49.21
  TOP w0.508: FB2.1 v1(156.9,27.18) ; v1(86.99,42.93) v1(86.99,41.91) ; R6.1 TP220.1
  TOP w0.762: v1(62.48,45.72) v1(64.01,45.72) 65.79,43.94 76.33,43.94 77.34,42.93 v1(86.99,42.93)
  BOTTOM w0.356: J2.67 160.2,46.86 v1(160.45,46.61) ; J2.69 160.83,46.86 v1(161.09,46.61)
  BOTTOM w0.508: TP220.1 158.04,26.29 157.78,26.29 v1(156.9,27.18) ; v1(86.99,41.91) v1(86.99,42.93) v1(86.99,45.97) 86.99,48.01 86.61,48.39 v1(86.61,49.4)
  BOTTOM w0.762: R387.2 32.4,47.08 32.56,47.24 60.96,47.24 v1(62.48,45.72) v1(64.01,45.72)
VBUS_5VDD_E: length 25.3
  TOP w0.254: U1.6 v1(101.35,46.74)
  TOP w0.305: CON60.A9 98.96,49.89 v1(98.93,49.91) 99.21,50.19 CON60.B4 ; CON60.B9 101.71,50.19 v1(101.98,49.91) 101.96,49.89 CON60.A4
  BOTTOM w0.381: C5.1 v1(101.98,49.91) ; C10.1 v1(98.93,49.91)
  BOTTOM w0.508: C5.1 101.47,50.67 101.09,51.05 99.67,51.05 98.93,50.32 v1(98.93,49.91) ; 102.49,46.74 v1(101.35,46.74) 101.57,46.96 101.57,48.51 101.51,48.57 101.51,49.44 v1(101.98,49.91)
  BOTTOM w0.762: J60.1 109.47,51.82 104.4,46.74 102.49,46.74
VDD_1V8: length 217.9
  TOP w0.254: v1(5.46,6.63) 4.09,8 3.17,8 2.92,7.75 v1(2.16,7.75) ; U4.K5 v3(147.53,26.88)
  TOP w0.305: U207.1 161.7,12.12
  TOP w0.356: J3.42 78.11,50.8 v1(78.23,50.67)
  TOP w0.381: v1(49.28,17.27) 49.28,17.96 U213.5 ; U207.1 v1(161.85,11.95) ; v1(19.56,44.7) v1(17.15,42.29) v1(16.64,41.78) ; v1(49.4,36.58) 49.4,35.89 U212.1 ; R303.2 v1(19.3,40.89) ; R14.1 v1(154.52,23.37) ; v1(77.34,50.67) 77.47,50.8 J3.40 ; v1(151.18,17.4) 151.94,18.16 v1(151.94,23.37) R17.1
  TOP w0.508: v1(133.4,45.85) 132.46,46.79 132.46,53.59 133.6,54.74 150.29,54.74 151.31,53.72 v1(151.31,53.47) ; v1(51.36,30.66) 50.72,30.02 v1(46.91,30.02) ; v1(50.16,13.97) 18.16,13.97 10.79,6.6 10.79,5.97 9.95,5.12 v1(8.63,5.12) 8.08,4.57 3.43,4.57 2.49,5.51 2.49,6.63 2.16,6.96 v1(2.16,7.75) ; v1(8.9,51.9) 8.36,51.36 5.79,51.36 v1(5.21,51.94) 3.05,49.78 R239.1 2.29,48.9 2.87,48.31 6.17,48.31 v1(8,46.48) ; v1(75.95,28.32) v1(72.39,28.32)
  L3_PWR w0.305: TP223.1 159.75,42.93 ; TP223.1 158.1,42.93 ; TP223.1 158.93,42.1
  BOTTOM w0.203: M4.2 9.37,3.79 8.98,4.18 M4.5 ; M1.5 162.28,5 162.69,5 163.39,4.3 M1.2 ; M3.2 8.05,53.11 8.46,53.11 9.16,52.41 M3.5 ; M2.5 130.15,5 130.56,5 131.19,4.37 131.62,4.37 M2.2
  BOTTOM w0.254: 146.61,23.5 146.81,23.99 146.81,24.97 146.93,25.08 C107.1 146.93,26.77 C108.1 147.03,26.88 v3(147.53,26.88)
  BOTTOM w0.279: U5.8 C25.1 152.67,14.7 C26.1 ; R30.1 153.97,13.34 v1(153.59,12.95) ; R214.2 v1(138.99,25.65)
  BOTTOM w0.305: C246.1 C247.1 5.21,51.56 v1(5.21,51.94) ; C244.1 C245.1 v1(46.91,30.02) ; R237.1 v1(51.36,30.66)
  BOTTOM w0.381: M3.5 9.92,52.09 C240.1 C241.1 v1(8.9,51.9) ; J2.40 v1(151.31,53.47) ; 2.41,5.84 2.41,4.62 U211.5 ; U208.1 132.89,12.81 C239.1 ; C244.1 48.56,29.06 U209.5 ; v1(151.94,23.37) v1(154.52,23.37) ; U205.5 132.64,44.53 C232.1 ; U210.5 4.01,52.22 C246.1 ; C270.1 62.1,22.52 U221.1 ; J2.42 v1(151.94,53.47) ; M4.5 7.61,4.94 C242.1 C243.1 v1(8.63,5.12) ; C38.1 v1(162.36,8) ; C253.1 v1(49.28,17.27) ; C237.1 v1(161.85,11.95) ; C251.1 v1(49.4,36.58) ; R383.2 v1(142.93,9.65)
  BOTTOM w0.508: 149.66,16.76 150.55,16.76 v1(151.18,17.4) ; 149.66,16.76 R287.2 150.16,14.73 v1(150.67,14.22) 151.15,14.7 C26.1 ; 149.66,16.76 148.77,17.65 148.77,18.57 146.86,20.47 146.86,22.1 146.61,22.35 R217.2 146.61,23.5 ; C232.1 v1(133.4,45.85) ; 2.41,5.84 2.41,7.49 v1(2.16,7.75) ; v1(132,9.52) 132.26,9.78 C239.1 ; 15.49,41.4 15.49,43.43 12.95,45.97 8.51,45.97 v1(8,46.48) ; C270.1 62.1,20.19 ; M1.5 162.16,5.72 162.36,5.92 C41.1 C38.1 ; R294.1 v1(72.39,28.32) ; M2.5 130.03,5.72 130.23,5.92 C40.1 C39.1 v1(130.23,8.08) ; R381.2 R379.2 ; R241.1 v1(5.46,6.63)
  vias: v1(20.45,44.7) v1(152.07,12.19) v1(153.09,12.19) v1(153.97,12.19)
VDD_OPI: length 28.6
  TOP w0.305: v1(144.59,18.36) U215.B4 ; U215.D1 v1(142.59,21.36) ; U215.E4 v1(140.59,17.36)
  TOP w0.381: v1(147.93,12.54) 147.55,12.92 147.55,14.94 147.12,15.36 v1(146.59,15.36) 146.23,15.72 144.93,15.72 144.57,15.36 142.02,15.36 141.51,15.87 141.51,16.41 141.58,16.48 141.58,17.37 U215.E4 141.6,18.37 141.6,20.37 U215.D1
  L3_PWR w0.254: 141.83,17.86 144.09,17.86
  L3_PWR w0.381: 141.83,17.86 141.34,17.36 v1(140.59,17.36) ; 144.09,17.86 v1(144.59,18.36)
  BOTTOM w0.254: R282.1 145.09,17.86 v1(144.59,18.36)
  BOTTOM w0.305: v1(144.59,18.36) 144.59,18.35 C257.1 ; C258.1 v1(142.59,21.36) ; R288.1 146.1,15.85 v1(146.59,15.36) ; C255.1 v1(140.59,17.36)
  BOTTOM w0.381: R280.1 v1(142.59,21.36)
  BOTTOM w0.508: R287.1 R286.2 C256.1 v1(147.93,12.54)
VDD_QSPI: length 6
  TOP w0.381: U216.8 v1(141.03,10.71)
  BOTTOM w0.381: R382.2 R383.1 C259.1 140.1,10.66 C260.1 v1(141.03,10.71) R283.1
VDD_SOC_IN: length 8.6
  TOP w0.127: U4.H9 v3(146.88,30.13)
  TOP w0.254: U4.F8 v3(144.93,29.48) 145.25,29.8 U4.F9 ; U4.F7 v3(144.93,28.18) 145.25,27.85 U4.F6 ; U4.G9 v3(146.23,30.13) ; U4.J5 v3(146.88,27.53) U4.H6 ; U4.G6 v3(145.58,27.53) ; U4.J9 v3(146.88,30.13)
  BOTTOM w0.254: C101.1 146.22,30.12 v3(146.23,30.13) ; C92.1 v3(145.58,27.53) ; C90.1 144.45,28.18 v3(144.93,28.18) ; C95.1 146.3,29.55 v3(146.88,30.13) ; v3(144.93,29.48) 144.91,29.46 C94.1 ; C96.1 146.83,27.49 v3(146.88,27.53)
  vias: v1(148.77,19.68) v1(149.4,19.68) v1(150.16,19.68) v1(150.8,19.68)
VDD_USB_3V: length 7.9
  TOP w0.127: U4.K8 v3(148.18,29.48)
  BOTTOM w0.102: v3(148.18,29.48) 148.69,29.99 148.69,30.61 149,30.91
  BOTTOM w0.254: C84.1 148.17,29.49 v3(148.18,29.48) ; 149,30.91 149,34.54 v4(149.18,34.98) 149.48,35.28 149.48,35.67 C88.1
ANT_50E: length 2.2
  TOP w0.635: C1.1 C3.1 U2.2
AUDIO_SD: length 30.5
  TOP w0.102: v1(141.78,50.81) 140.64,49.67 140.64,49.33 138.47,47.16 138.47,45.22 137.06,43.81 v1(137.06,33.76) ; U4.E8 144.28,28.83 v3(143.63,28.83)
  BOTTOM w0.102: v3(143.63,28.83) 142.8,28.83 141.68,29.95 141.68,30.66 140.28,32.05 139.78,32.05 138.56,33.27 137.54,33.27 v1(137.06,33.76) ; J2.10 v1(141.78,50.81)
AUDIO_SD_EXT: length 75
  TOP w0.102: v1(91.06,16.56) 88.44,19.18 66.8,19.18 66.55,19.43 v1(66.55,20.07) ; v1(67.94,50.67) J3.10
  BOTTOM w0.102: v1(67.94,50.67) 67.94,49.78 67.64,49.48 67.64,47.29 68.45,46.48 68.45,39.75 67.82,39.12 67.82,31.01 65.15,28.35 65.15,21.46 v1(66.55,20.07) ; U6.C2 R79.1 97.28,10.34 v1(91.06,16.56)
B: length 1.9
  TOP w0.102: D60.4 v1(163,19.95)
  BOTTOM w0.102: R81.2 162.99,19.94 v1(163,19.95)
BT_DEV_WAKE: length 1.4
  TOP w0.102: U2.6 TP2.1
BT_HOST_WAKE: length 21.9
  TOP w0.102: v1(144.32,50.81) 142.89,49.38 142.89,48.89 141.71,47.7 141.71,46.38 140.11,44.79 140.11,40.99 141.99,39.12 141.99,36.06 142.65,35.39 U4.B14
  BOTTOM w0.102: J2.18 v1(144.32,50.81)
BT_HOST_WAKE_EXT: length 39.5
  TOP w0.102: v1(70.48,50.67) J3.18 ; v1(66.67,22.73) 72.01,22.73 v1(72.64,22.1) TP3.1
  BOTTOM w0.102: v1(70.48,50.67) 70.48,50.04 70.13,49.68 70.13,41.81 69.93,41.61 69.93,40.87 70.23,40.56 70.23,30.61 66.67,27.05 v1(66.67,22.73) ; v1(72.64,22.1) R301.1
BT_HOST_WAKE_LS: length 4.8
  BOTTOM w0.102: U221.2 61.18,23.21 60.58,22.61 v4(60.55,22.61) R295.2 R300.2 R352.2
BT_REG_ON: length 21
  TOP w0.102: v1(145.59,50.81) 144.32,49.54 144.32,48.97 142.9,47.54 142.9,46.3 142.24,45.64 142.24,40.69 142.09,40.54 142.09,40.03 142.7,39.42 142.7,36.3 143.21,35.79 143.21,34.96 143.3,34.86 U4.C14
  BOTTOM w0.102: J2.22 v1(145.59,50.81)
BT_REG_ON_EXT: length 28.8
  TOP w0.102: v1(71.75,50.67) J3.22
  BOTTOM w0.102: v1(71.75,50.67) 72.77,49.66 72.77,40.77 72.59,40.59 72.59,39.65 72.77,39.47 72.77,29.59 73.66,28.7 R319.1 v2(72.64,26.54) R339.1
BT_REG_ON_LS: length 74.4
  TOP w0.102: v1(60.45,25.65) 59.74,25.65 58.57,24.49 41.58,24.49 41.27,24.79 39.92,24.79 38.9,23.77 19.66,23.77 v1(17.27,26.16)
  BOTTOM w0.102: R310.2 v1(60.45,25.65) 60.94,25.16 U221.5 ; R338.1 1.9,40.01 1.4,39.5 1.4,33.66 2.67,32.38 8.59,32.38 12.01,28.96 14.27,28.96 16.93,26.31 v1(17.27,26.16)
BT_UART1_CTS: length 20.4
  TOP w0.102: v1(148.77,50.04) 148.23,49.5 148.23,48.68 147.19,47.64 147.19,44.96 146.76,44.53 146.76,39.4 146.58,39.22 146.58,37.44 146.41,37.26 146.41,35.59 146.61,35.38 146.61,33.11 U4.H14
  BOTTOM w0.102: v1(148.77,50.04) 148.13,49.4 J2.29
BT_UART1_CTS_EXT: length 30
  TOP w0.102: v1(74.3,45.97) J3.29 ; v1(65.41,29.46) 74.04,29.46 v1(74.55,29.97)
  BOTTOM w0.102: v1(74.55,29.97) 74.02,30.51 74.02,35.48 73.63,35.86 73.63,39.8 73.69,40.06 73.69,40.92 74.04,41.27 74.04,45.06 74.3,45.31 v1(74.3,45.97) ; v1(65.41,29.46) TP9.1 64.08,30.03 63.95,30.03 R292.2
BT_UART1_CTS_LS: length 30.6
  TOP w0.102: v1(55.5,29.46) 56.13,30.1 56.13,31.75 55.88,32 54.74,32 53.98,32.77 47.73,32.77 43.44,28.47 34.77,28.47 v1(33.66,29.59)
  BOTTOM w0.102: R348.2 v1(33.66,29.59) R345.2 ; v1(55.5,29.46) 55.81,29.59 R370.1
BT_UART1_RTS: length 22.4
  TOP w0.102: v1(155.5,46.61) 154.94,46.05 153.57,46.05 153.21,45.69 153.21,44.27 153.9,43.59 153.9,38.43 151.46,35.99 151.46,35.26 151.03,34.83 151.03,32.55 150.58,32.1 150.37,32.1 150.15,31.88 150.15,31.67 149.93,31.45 149.72,31.45 149.5,31.23 149.5,31.02 149.28,30.8 148.95,30.8 148.61,30.45 U4.L10
  BOTTOM w0.102: J2.53 155.75,46.86 v1(155.5,46.61)
BT_UART1_RTS_EXT: length 32.7
  TOP w0.102: v1(82.17,45.97) 81.91,46.23 J3.53 ; v1(65.41,33.53) 81.28,33.53 v1(81.53,33.78)
  BOTTOM w0.102: v1(82.17,45.97) 82.3,45.85 82.3,37.85 81.53,37.08 v1(81.53,33.78) ; R371.2 64.26,33.15 TP6.1 v1(65.41,33.53)
BT_UART1_RTS_LS: length 25.6
  TOP w0.102: v1(55.5,32.51) 54.86,33.15 47.61,33.15 43.29,28.83 36.07,28.83 v1(35.31,29.59)
  BOTTOM w0.102: R349.2 v1(35.31,29.59) R342.2 ; v1(55.5,32.51) 55.75,32.26 R289.1
BT_UART1_RXD: length 21.4
  TOP w0.102: v1(152.58,50.81) 152.58,50.37 153.26,49.68 153.26,49.12 152.5,48.36 152.5,43.98 152.58,43.9 TP212.1 151.81,42.04 151.81,40.38 151.51,40.08 151.51,38.92 150.34,37.75 150.34,36.83 148.5,34.99 U4.L14
  BOTTOM w0.102: J2.44 v1(152.58,50.81)
BT_UART1_RXD_EXT: length 39.9
  TOP w0.102: v1(77.47,31.37) 76.96,30.86 v1(65.41,30.86) ; v1(78.36,54.1) 78.74,53.72 J3.44
  BOTTOM w0.102: R291.2 64.13,31.37 TP8.1 v1(65.41,30.86) ; v1(77.47,31.37) 77.72,31.62 77.72,37.52 77.6,37.64 77.6,39.32 77.77,39.5 77.77,41.65 77.95,41.83 77.95,44.57 78.11,44.72 78.11,46.29 78.77,46.96 78.77,50.57 78.89,50.69 78.89,53.58 v1(78.36,54.1)
BT_UART1_RXD_LS: length 30.6
  TOP w0.102: v1(55.5,30.48) 54.99,30.99 52.55,30.99 52.33,31.22 48.17,31.22 47.99,31.04 47.07,31.04 43.8,27.76 32.18,27.76 v1(30.35,29.59)
  BOTTOM w0.102: R369.1 v1(55.5,30.48) ; R344.2 v1(30.35,29.59) R346.2
BT_UART1_TXD: length 16.2
  TOP w0.102: U4.K14 147.85,36.37 148.13,36.65 148.13,38.76 148.18,38.81 148.18,41 148.74,41.55 148.74,41.83 148.51,42.06 TP211.1 148.84,43.71 149.78,44.65 149.78,46.3 v1(149.66,46.61)
  BOTTOM w0.102: J2.35 150.04,46.71 149.94,46.61 v1(149.66,46.61)
BT_UART1_TXD_EXT: length 30.6
  TOP w0.102: v1(74.65,32.84) 66.12,32.84 v1(65.41,32.13) ; v1(76.2,49.4) J3.35
  BOTTOM w0.102: v1(74.65,32.84) 74.65,35.76 74.37,36.04 74.37,39.4 74.85,39.88 74.85,41.14 75.41,41.7 75.41,45.19 75.72,45.49 75.72,47.27 76.2,47.75 v1(76.2,49.4) ; v1(65.41,32.13) TP7.1 64.13,32.13 64.01,32.26 R372.2
BT_UART1_TXD_LS: length 29.3
  TOP w0.102: v1(32,29.59) 33.48,28.12 43.65,28.12 46.93,31.39 47.84,31.39 48.08,31.63 48.08,31.97 48.37,32.26 52.88,32.26 53.64,31.5 v1(55.5,31.5)
  BOTTOM w0.102: R347.2 v1(32,29.59) R343.2 ; R290.1 55.81,31.37 v1(55.5,31.5)
CC1: length 2.3
  TOP w0.102: CON60.A5 101.46,48.53 101.85,48.13 v1(102.23,48.13)
  BOTTOM w0.102: R5.1 v1(102.23,48.13)
CC2: length 1.8
  TOP w0.102: v1(99.31,51.56) 99.71,51.17 CON60.B5
  BOTTOM w0.102: R3.1 v1(99.31,51.56)
DCDC_3V3: length 99
  TOP w0.127: U4.J10 v3(146.88,30.78)
  TOP w0.254: U4.E9 v3(144.28,30.13) ; U4.K4 v3(148.18,26.23) ; U4.N14 v3(149.8,33.54) ; U4.M9 v3(149.48,29.48) ; U4.P12 v3(151.1,31.75) ; U4.L1 v3(148.83,24.28) ; U4.F10 v3(144.93,30.78) ; U4.L2 v3(148.83,24.93)
  TOP w0.356: v1(76.2,54.1) J3.36 ; v1(76.83,54.1) J3.38
  TOP w0.381: v1(51.56,17.27) 51.56,17.96 U213.1 ; R41.1 v1(137.85,34.8) ; v1(163.25,12.57) 163.25,12.02 U207.5 ; v1(51.56,36.58) 51.56,35.89 U212.5 ; v1(76.45,50.67) 76.2,50.93 J3.36 ; R302.1 v1(22.1,40.01) ; U203.1 157.47,9.2 157.66,9.02 158.67,9.02 C218.1 159.44,10.07 U203.3 ; R314.1 v1(47.88,11.68)
  TOP w0.508: Y1.4 Y1.1 10.33,46.74 v1(9.4,46.74) C16.1 ; J64.13 v1(29.92,54.48) ; v1(11.43,17.02) C278.1 11.68,18.54 C279.1 L1.1 ; J62.1 v1(16.76,50.32) ; SW64.1 v1(146.01,6.6)
  L3_PWR w0.305: 148.51,44.64 TP215.1
  L3_PWR w0.508: 150.16,44.7 149.4,45.47 TP215.1 ; 148.13,46.74 148.51,46.36 TP215.1 ; 146.86,44.2 148.13,45.47 TP215.1
  BOTTOM w0.254: C79.1 149.8,34.18 v3(149.8,33.54) 149.8,32.91 C78.1 ; R216.1 v3(142.98,25.58) ; R71.1 v3(148.24,23.75) ; v3(144.93,30.78) 144.29,31.41 C85.1 ; C112.1 148.18,26.8 v3(148.18,26.23) ; C72.1 151.65,31.75 v3(151.1,31.75) 151.1,32.22 C73.1 ; v3(146.88,30.78) 146.86,30.79 C106.1 ; v3(144.28,30.13) 144.28,29.56 C97.1 ; C76.1 149.44,29.52 v3(149.48,29.48) ; U217.1 60.19,34.03 C261.1 ; v1(55.63,33.4) 55.88,33.15 R374.2
  BOTTOM w0.279: v1(138.99,26.42) 139.24,26.67 R215.1
  BOTTOM w0.305: U3.7 65.16,9.52 R312.2
  BOTTOM w0.356: J2.36 v1(150.04,53.47) ; J2.38 v1(150.67,53.47) ; C87.1 149.19,23.92 v3(148.83,24.28) ; C102.1 149.05,25.44 149.05,25.15 v3(148.83,24.93)
  BOTTOM w0.381: R376.1 v1(56.77,35.31) ; C100.1 151.31,35.69 v1(150.99,35.37) ; R69.1 157.75,34.84 v1(157.53,35.05) ; C250.1 v1(51.56,36.58) ; U221.14 67.94,22.52 C269.1 ; L4.2 69.85,14.22 70.61,13.46 70.61,8.64 69.34,7.37 66.17,7.37 65.41,8.13 R312.2 ; C236.1 v1(163.25,12.57) ; C261.1 v1(61.21,34.29) ; R40.1 v1(137.85,29.59) ; R32.1 v1(137.85,28.45) ; U208.5 136.19,12.81 C238.1 ; R218.1 v1(42.04,29.46) ; R382.1 v1(142.93,8.76) ; C252.1 v1(51.56,17.27) ; C233.1 132.65,42.03 U205.1 ; C225.1 156.9,10.67 v1(156.64,10.41) ; v1(156.64,9.65) 156.9,9.4 C226.1
  BOTTOM w0.508: R380.1 v1(55.75,25.65) ; U214.5 C254.1 v1(129.59,36.2) ; R70.1 v1(130.48,21.72) ; v1(16.76,50.32) 16.89,50.19 C35.1 ; R62.2 v1(149.28,9.65) ; R23.1 v1(151.18,9.14) ; R22.1 v1(143.94,35.18) ; R311.1 v1(72.39,27.43) ; R307.1 v1(72.39,25.65) ; R298.1 v1(72.39,22.99) ; R378.1 v1(55.75,22.61) ; R15.1 R16.1 v1(149.66,40.64) ; v1(133.91,41.4) 133.65,41.15 C233.1 ; C238.1 v1(136.83,12.32) ; C269.1 v1(68.83,21.08) ; R297.1 v1(72.39,21.21) ; R286.1 v1(148.64,15.49)
  vias: v1(68.71,9.65) v1(68.71,9.02) v1(69.34,9.65) v1(69.34,9.02)
DCDC_FB: length 2.2
  BOTTOM w0.102: U3.8 64.65,9.28 64.39,9.02 R315.1
DCDC_SW: length 0.9
  BOTTOM w0.254: 65.79,12.45 v4(65.77,12.43) 65.65,12.31 U3.3
DM: length 7.3
  TOP w0.102: v1(100.84,49.91) 100.71,50.23 CON60.B7 ; U1.2 100.2,48.01 v1(99.96,48.26) CON60.A7
  BOTTOM w0.102: v1(100.84,49.91) 100.43,50.32 99.84,50.32 99.67,50.15 99.67,49.36 100.36,48.67 100.36,48.36 100.25,48.26 v1(99.96,48.26) 100.18,48.04 L60.4
DP: length 5.3
  TOP w0.102: CON60.B6 100.21,50.23 v1(100.08,49.91) ; U1.1 100.7,48.01 v1(100.96,48.26) CON60.A6
  BOTTOM w0.102: v1(100.08,49.91) 100.08,49.46 100.71,48.82 100.71,48.51 v1(100.96,48.26) 100.74,48.04 L60.1
G: length 1.9
  TOP w0.102: D60.3 v1(163,16.26)
  BOTTOM w0.102: R82.2 162.99,16.26 v1(163,16.26)
GPIO_AD_B0_01: length 24.3
  TOP w0.102: v1(145.5,39.24) 145.5,39.64 145.47,39.67 145.47,42.19 145.64,42.37 145.64,43.54 145.34,43.84 145.34,45.14 146,45.8 146,48.6 146.16,48.77 146.16,49.62 146.63,50.09 147.04,50.09 v1(147.75,50.8)
  TOP w0.127: U4.H10 v3(146.23,30.78)
  BOTTOM w0.102: v1(147.75,50.8) 147.5,51.05 J2.28 ; v1(145.5,39.24) 146.63,38.11 146.63,33.05 146.18,32.59 146.18,31.95 145.85,31.62 145.85,31.16 v3(146.23,30.78)
GPIO_AD_B0_01_EXT: length 45.3
  TOP w0.102: v1(32.72,54.69) 32.46,54.43 J64.11 ; v1(73.28,54.1) 73.66,53.72 J3.28
  BOTTOM w0.102: v1(73.28,54.1) 72.42,54.97 32.99,54.97 v1(32.72,54.69)
GPIO_AD_B0_02: length 20.9
  TOP w0.102: v1(154.74,46.61) 154.69,46.66 153.47,46.66 152.86,46.05 152.86,44.12 153.54,43.44 153.54,38.63 151.33,36.42 151,36.42 149.41,34.83 149.41,33.22 149.46,33.18 149.46,31.51 149.15,31.21 U4.M11
  BOTTOM w0.102: v1(154.74,46.61) 155.12,46.99 J2.51
GPIO_AD_B0_02_EXT: length 58.4
  TOP w0.102: J64.8 37.54,45.39 38.35,44.58 53.73,44.58 57.21,41.1 63.77,41.1 65.22,39.65 73.41,39.65 73.69,39.93 73.69,40.13 73.84,40.28 80.04,40.28 v1(80.39,40.64) ; v1(81.27,49.38) 81.28,49.37 J3.51
  BOTTOM w0.102: v1(81.27,49.38) 81.27,47.59 80.16,46.48 80.16,45.63 80.39,45.4 v1(80.39,40.64)
GPIO_AD_B0_03: length 23.4
  TOP w0.102: v1(146.86,50.81) 146.5,50.44 146.49,50.44 145.77,49.73 145.77,48.92 145.02,48.17 145.02,46.18 143.89,45.05 143.89,43.74 143.64,43.48 143.64,42.32 143.87,42.09 143.87,42.01 144.48,41.4 144.48,38.38 145.21,37.65 145.21,35.05 145.64,34.63 145.64,33.33 145.58,33.27 145.58,31.43 U4.G11
  BOTTOM w0.102: J2.26 v1(146.86,50.81)
GPIO_AD_B0_03_EXT: length 49.8
  TOP w0.102: v1(73.28,50.67) 73.02,50.93 J3.26 ; v1(73.18,40.13) 72.62,40.13 72.52,40.03 65.34,40.03 63.92,41.45 57.36,41.45 53.88,44.93 41.2,44.93 40.08,46.05 J64.6
  BOTTOM w0.102: v1(73.18,40.13) 73.18,40.92 73.69,41.43 73.69,45.24 73.79,45.34 73.79,48.39 74.17,48.77 74.17,49.79 v1(73.28,50.67)
GPIO_AD_B0_04: length 65.9
  TOP w0.102: v1(134.16,36.7) 134.16,32.86 133.63,32.32 133.63,27.78 131.78,25.93 131.78,21.95 133.17,20.55 133.17,16.36 133.5,16.03 133.5,10.07 133.63,9.95 133.63,9.49 133.77,9.35 v1(133.77,7.96) ; U4.F11 v3(144.93,31.43) ; v1(147.75,6.73) J61.3
  BOTTOM w0.102: v1(133.77,7.96) 134.17,7.8 136.35,7.8 136.58,8.03 139.51,8.03 140.36,7.18 140.38,7.18 140.42,7.14 145.78,7.14 146.24,6.95 146.46,6.73 v1(147.75,6.73) ; v1(134.16,36.7) 135.81,36.7 137.46,38.35 140.13,38.35 140.64,37.85 144.2,37.85 R21.2 R22.2 145.77,35.13 145.77,33.05 145.64,32.92 145.64,32.14 v3(144.93,31.43)
GPIO_AD_B0_05: length 73.8
  TOP w0.102: v1(134.85,37.44) 134.85,33.04 133.99,32.18 133.99,27.64 132.13,25.78 132.13,22.1 133.53,20.7 133.53,16.51 133.86,16.18 133.86,10.22 133.99,10.09 133.99,9.64 134.13,9.49 134.13,8.67 v1(134.42,8.38) ; v1(145.59,37.97) 145.59,35.18 145.9,34.87 U4.G14 ; v1(153.97,9.14) 153.54,8.71 J61.1 v1(152.83,6.6)
  BOTTOM w0.102: v1(152.83,6.6) 152.83,7.32 152.65,7.49 147.73,7.49 147.24,7.29 146.35,7.29 145.85,7.49 140.55,7.49 139.66,8.38 136.43,8.38 136.21,8.15 134.65,8.15 v1(134.42,8.38) ; R24.2 R23.2 v1(153.97,9.14) ; v1(134.85,37.44) 135.84,37.44 137.11,38.71 140.61,38.71 140.89,38.43 143.84,38.43 144.37,38.96 145.19,38.96 145.59,38.56 v1(145.59,37.97)
GPIO_AD_B1_04: length 21.1
  TOP w0.102: v1(151.31,49.27) 151.31,43.89 150.27,42.85 150.27,41.38 150.22,41.33 150.22,40.26 149.76,39.8 149.76,38.27 149.12,37.63 149.12,36.68 148.77,36.32 v1(148.39,36.32) ; U4.L12 v3(148.18,31.43)
  BOTTOM w0.102: v3(148.18,31.43) 148.39,31.64 v1(148.39,36.32) ; J2.39 v1(151.31,49.27)
GPIO_AD_B1_04_EXT: length 35.4
  TOP w0.102: J64.1 63.53,52.42 65.78,50.16 76.96,50.16 77.47,49.66 J3.39
GPIO_AD_B1_12: length 20.3
  TOP w0.102: v1(148.77,49.27) 148.77,48.64 147.55,47.42 147.55,44.73 147.12,44.3 147.12,39.25 147.07,39.2 147.07,39.2 147.04,39.17 147.04,37.26 146.79,37 146.79,35.95 146.9,35.84 146.9,32.93 146.68,32.71 146.43,32.71 146.25,32.53 146.25,32.06 U4.H12
  BOTTOM w0.102: J2.31 v1(148.77,49.27)
